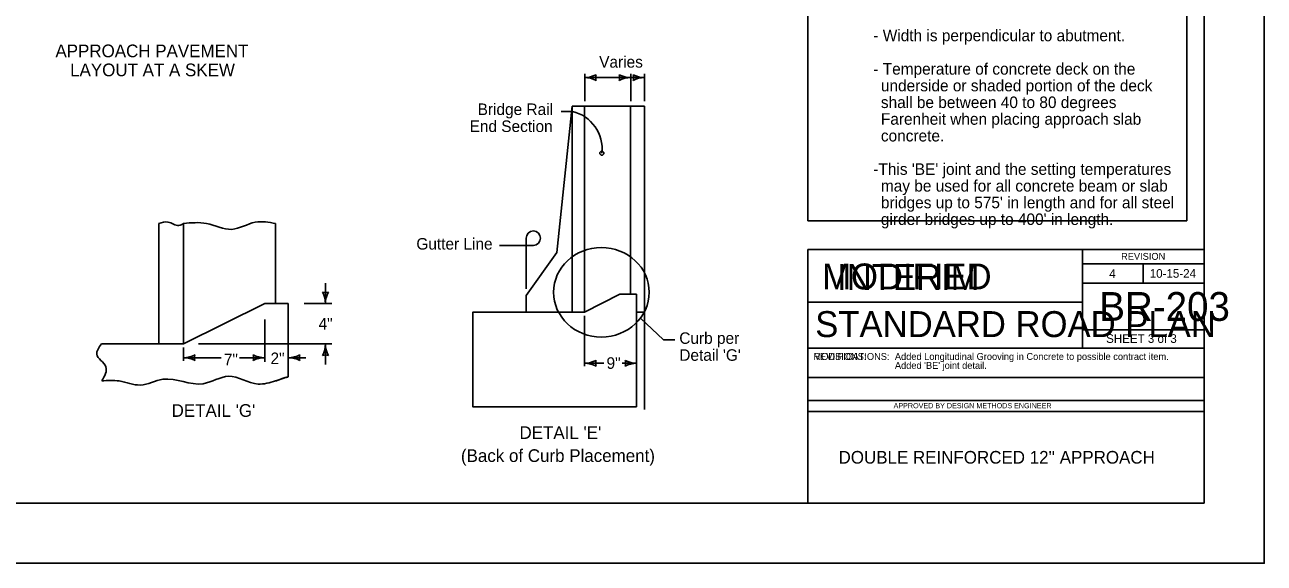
# Model space of a CAD drawing. Extents: x 10130 to 81668, y 5440 to 21644.
# Drawn here: x 18491 to 20643, y 5440 to 6374 of the extents above; entities that cross this region are included whole.
import ezdxf

# ---------------------------------------------------------------- set-up
doc = ezdxf.new("R2010")
doc.units = 0
for name, color, linetype in [('Cell', 7, 'Continuous'), ('dsnCellElements', 7, 'Continuous'), ('dsnNonPlotable', 7, 'Continuous'), ('dsnShtPlotShapeBatchPrint', 7, 'Continuous'), ('dsnstdblockInterim', 7, 'Continuous'), ('dsnStdBlockModified', 7, 'Continuous'), ('dsnStdBlockNotModified', 7, 'Continuous'), ('dsnStdBorder', 7, 'Continuous'), ('dsnStdLabel', 7, 'Continuous'), ('Level 1', 7, 'Continuous'), ('Level 5', 7, 'Continuous')]:
    doc.layers.add(name, color=color, linetype=linetype)

msp = doc.modelspace()

# ---------------------------------------------------------------- linework, layer by layer
at = {"layer": 'Cell'}
msp.add_lwpolyline([(17403.2, 7554.1), (20538.2, 7554.1), (20538.2, 5544.1), (17403.2, 5544.1)], close=True, dxfattribs=at)
at = {"layer": 'dsnCellElements'}
for p, q in [((19361.3, 5983.9), (19361.3, 6003.9)), ((19373.8, 5991.4), (19353.8, 5991.4))]:
    msp.add_line(p, q, dxfattribs=at)
msp.add_circle((19492.7, 6151.4), 3.54, dxfattribs=at)
msp.add_arc((19373.8, 6003.9), 12.5, 270, 180, dxfattribs=at)
at = {"layer": 'dsnNonPlotable'}
for p, q in [((19850.2, 7504.1), (19850.2, 6034.1)), ((20508.2, 7504.1), (20508.2, 6034.1)), ((20508.2, 6034.1), (19850.2, 6034.1))]:
    msp.add_line(p, q, dxfattribs=at)
at = {"layer": 'dsnShtPlotShapeBatchPrint'}
msp.add_lwpolyline([(17298.7, 5439.6), (20642.7, 5439.6), (20642.7, 8023.6), (17298.7, 8023.6)], close=True, dxfattribs=at)
at = {"layer": 'dsnStdBlockNotModified'}
for centre, radius, start, end in [((19462.6, 6325.2), 42.5, 270, 298.0725), ((19498.3, 6282.7), 16.4, 162.2666, 197.7334), ((19507.3, 6282.7), 16.4, 342.2666, 17.7333), ((19542.9, 6325.2), 42.5, 241.9275, 270), ((19531.2, 6282.7), 16.4, 342.2666, 17.7333), ((19566.9, 6325.2), 42.5, 241.9275, 270), ((19462.6, 6240.2), 42.5, 61.9275, 90), ((19542.9, 6240.2), 42.5, 90, 118.0725), ((19566.9, 6240.2), 42.5, 90, 118.0725), ((19012.9, 5925.8), 16.4, 252.2666, 287.7333), ((18970.4, 5890.2), 42.5, 360, 28.0725), ((19055.4, 5890.2), 42.5, 151.9275, 180), ((18970.4, 5820.3), 42.5, 331.9275, 360), ((19055.4, 5820.3), 42.5, 180, 208.0725), ((18766.4, 5838.9), 42.5, 270, 298.0725), ((18766.4, 5753.9), 42.5, 61.9275, 90), ((18802, 5796.4), 16.4, 162.2666, 197.7334), ((18871.8, 5796.4), 16.4, 342.2666, 17.7333), ((18907.5, 5838.9), 42.5, 241.9275, 270), ((18907.5, 5753.9), 42.5, 90, 118.0725), ((18948.4, 5838.9), 42.5, 270, 298.0725), ((18948.4, 5753.9), 42.5, 61.9275, 90), ((18984.1, 5796.4), 16.4, 162.2666, 197.7334), ((19012.9, 5784.7), 16.4, 72.2666, 107.7334), ((19462.6, 5829.2), 42.5, 270, 298.0725), ((19498.3, 5786.7), 16.4, 162.2666, 197.7334), ((19517.7, 5786.7), 16.4, 342.2666, 17.7333), ((19553.3, 5829.2), 42.5, 241.9275, 270), ((19462.6, 5744.2), 42.5, 61.9275, 90), ((19553.3, 5744.2), 42.5, 90, 118.0725)]:
    msp.add_arc(centre, radius, start, end, dxfattribs=at)
at = {"layer": 'dsnStdBorder'}
for p, q in [((19462.9, 6242), (19462.9, 6289.4)), ((19542.9, 6242), (19542.9, 6289.4)), ((19566.9, 6242), (19566.9, 6289.4)), ((19462.6, 6282.7), (19491.7, 6282.7)), ((19462.9, 6282.7), (19542.9, 6282.7)), ((19538.6, 6282.7), (19566.9, 6282.7)), ((19414.6, 5979), (19441.3, 6233)), ((19441.6, 6223.8), (19422.1, 6223.8)), ((19441.3, 6233), (19542.7, 6233)), ((19441.3, 6233), (19441.3, 5875.4)), ((19462.6, 6233), (19462.6, 5875.4)), ((19542.7, 6233), (19542.7, 5906.9)), ((19542.7, 6233), (19566.9, 6233)), ((19566.9, 6233), (19566.9, 5706.6)), ((18723.8, 6029.3), (18723.8, 5820.3)), ((18766.4, 6029.3), (18766.4, 5820.3)), ((18926.4, 6029.3), (18926.4, 5890.2)), ((19314.9, 5991.4), (19353.8, 5991.4)), ((19361.3, 5916), (19361.3, 5983.9)), ((19361.3, 5904.3), (19414.6, 5979)), ((18926.4, 5946.7), (18926.4, 5890.2)), ((19012.9, 5925.9), (19012.9, 5890.2)), ((19542.7, 5938.6), (19542.7, 5906.9)), ((19361.3, 5875.3), (19361.3, 5904.3)), ((19552.9, 5906.9), (19524, 5906.9)), ((19524, 5906.9), (19552.9, 5906.9)), ((19552.9, 5711.2), (19552.9, 5906.9)), ((19552.9, 5906.9), (19552.9, 5711.2)), ((18948.4, 5890.2), (18907.7, 5890.2)), ((18948.4, 5762.9), (18948.4, 5890.2)), ((18975.8, 5890.2), (19023.7, 5890.2)), ((19552.9, 5875.4), (19566.9, 5875.4)), ((18907.5, 5862.9), (18907.5, 5789)), ((19462.6, 5781.5), (19462.6, 5868.8)), ((19559.6, 5865), (19599.6, 5827.3)), ((18765.2, 5820.3), (18624.2, 5820.2)), ((18648.6, 5820.2), (18624.2, 5820.2)), ((18624.5, 5820.3), (18670.4, 5820.2)), ((18670.4, 5820.2), (18648.6, 5820.2)), ((18766.3, 5820.2), (18670.4, 5820.2)), ((18670.4, 5820.2), (18766.3, 5820.2)), ((18766.4, 5820.3), (18765.2, 5820.3)), ((18766.3, 5813.9), (18766.3, 5790.9)), ((18792.2, 5820.3), (19023.7, 5820.3)), ((19012.9, 5820.3), (19012.9, 5784.6)), ((19599.6, 5827.3), (19619.4, 5827.3)), ((18766.4, 5796.4), (18832.1, 5796.4)), ((18863.4, 5796.4), (18907.5, 5796.4)), ((18948.4, 5796.4), (18978.8, 5796.4)), ((19462.6, 5786.7), (19496.3, 5786.7)), ((19528.1, 5786.7), (19553.3, 5786.7))]:
    msp.add_line(p, q, dxfattribs=at)
for points in [[(19462.6, 5875.4), (19524, 5906.9)], [(19462.6, 5875.4), (19524, 5906.9)], [(18907.7, 5890.2), (18766.4, 5820.3), (18766.3, 5820.2)], [(18766.3, 5820.2), (18907.7, 5890.2)], [(18948.4, 5890.2), (18926.4, 5890.2), (18907.7, 5890.2)], [(18948.4, 5762.9), (18948.4, 5762.9), (18948.4, 5890.2)], [(19552.9, 5711.2), (19268.6, 5711.2), (19268.6, 5875.4), (19414.7, 5875.3), (19462.6, 5875.4)], [(19552.9, 5711.2), (19268.6, 5711.2), (19268.6, 5875.4), (19414.7, 5875.3), (19462.6, 5875.4)]]:
    msp.add_lwpolyline(points, dxfattribs=at)
msp.add_arc((19426.5, 6158.9), 66.7, 353.5756, 76.8823, dxfattribs=at)
msp.add_ellipse((19491.9, 5909.9), major_axis=(83, 0), ratio=0.93542, dxfattribs=at)
for points in [[(18723.8, 6029.3), (18739.4, 6031.8), (18758.5, 6025.9), (18766.4, 6029.3)], [(18766.4, 6029.3), (18806.5, 6029.3), (18850.2, 6019.2), (18891.1, 6031.5), (18926.4, 6029.3)], [(18624.2, 5820.2), (18615.9, 5802.6), (18631.7, 5780.5), (18624.5, 5756)], [(18624.2, 5820.2), (18615.9, 5802.6), (18631.7, 5780.5), (18624.5, 5756)], [(18624.5, 5756), (18655, 5756), (18691.2, 5748.9), (18730.8, 5758.9), (18800.8, 5751.3), (18844.6, 5764.1), (18895.9, 5750.7), (18926.4, 5756)], [(18624.5, 5756), (18655, 5756), (18691.2, 5748.9), (18730.8, 5758.9), (18800.8, 5751.3), (18844.6, 5764.1), (18895.9, 5750.7), (18926.4, 5756)], [(18926.4, 5756), (18940.5, 5761), (18945.8, 5762.6)]]:
    msp.add_spline(points, degree=3, dxfattribs=at)
msp.add_open_spline([(18926.4, 5756), (18927.3, 5756.2), (18928.3, 5756.5), (18929.2, 5756.8), (18930.1, 5757.2), (18931, 5757.5), (18931.9, 5757.8), (18933.7, 5758.5), (18935.6, 5759.3), (18937.4, 5760), (18939.2, 5760.7), (18941, 5761.3), (18942.9, 5761.9), (18943.8, 5762.1), (18944.7, 5762.3), (18945.6, 5762.5), (18946.1, 5762.6), (18946.5, 5762.7), (18947, 5762.8), (18947.5, 5762.8), (18947.9, 5762.9), (18948.4, 5762.9)], degree=3, dxfattribs=at)
at = {"layer": 'dsnStdLabel'}
for p, q in [((20327.3, 5984.1), (20327.3, 5892.8)), ((20327.3, 5959.2), (20538.2, 5959.2)), ((20432.7, 5959.2), (20432.7, 5926)), ((20327.3, 5926), (20538.2, 5926)), ((19850.2, 5892.8), (20327.3, 5892.8)), ((20327.3, 5892.8), (20327.3, 5812.8)), ((20538.2, 5845), (20327.3, 5845)), ((19850.2, 5812.8), (20538.2, 5812.8)), ((19850.2, 5761.8), (20538.2, 5761.8)), ((19850.2, 5721.8), (20538.2, 5721.8)), ((19850.2, 5702.8), (20538.2, 5702.8))]:
    msp.add_line(p, q, dxfattribs=at)
msp.add_lwpolyline([(19850.2, 5984.1), (20538.2, 5984.1), (20538.2, 5544.1), (19850.2, 5544.1)], close=True, dxfattribs=at)
msp.add_lwpolyline([(19850.2, 5984.1), (20538.2, 5984.1), (20538.2, 5544.1), (19850.2, 5544.1)], close=True, dxfattribs=at)

# ---------------------------------------------------------------- texts
at = {"layer": 'dsnstdblockInterim'}
msp.add_text('INTERIM', height=45, dxfattribs=at).set_placement((19901.1, 5913.8))
at = {"layer": 'dsnStdBlockModified'}
msp.add_text('(Back of Curb Placement)', height=22, dxfattribs=at).set_placement((19248.1, 5615.4))
at = {"layer": 'dsnStdBlockNotModified'}
msp.add_text('REVISIONS:', height=12, dxfattribs=at).set_placement((19860.2, 5792.5))
at = {"layer": 'dsnStdBorder'}
for s, height, p in [('APPROACH PAVEMENT', 22, (18544.1, 6318)), ('LAYOUT AT A SKEW', 22, (18569.6, 6285)), ('Varies', 20, (19488.1, 6299.9)), ('Bridge Rail ', 20, (19277.1, 6217.7)), ('End Section', 20, (19263.1, 6188.2)), ('Gutter Line', 20, (19170.7, 5984.1)), ('4"', 20, (19000.9, 5845.2)), ('Curb per', 20, (19627.2, 5820.4)), ("Detail 'G'", 20, (19627.2, 5791)), ('7"', 20, (18836.5, 5783.3)), ('2"', 20, (18917.5, 5785.3)), ('9"', 20, (19500.9, 5777.1)), ("DETAIL 'G'", 22, (18745.8, 5693.7)), ("DETAIL 'E'", 22, (19349.7, 5655.4))]:
    msp.add_text(s, height=height, dxfattribs=at).set_placement(p)
at = {"layer": 'dsnStdLabel'}
for s, height, p in [('REVISION', 12, (20394.2, 5966.3)), ('4', 15, (20373.6, 5934.8)), ('10-15-24', 15, (20444, 5935.2)), ('BR-203', 50, (20356.4, 5860.3)), ('STANDARD ROAD PLAN', 45.001, (19863.2, 5832.2)), ('SHEET 3 of 3', 15, (20368.2, 5822.1)), ('Added Longitudinal Grooving in Concrete to possible contract item. ', 12, (20001.5, 5792.5)), ("Added 'BE' joint detail.", 12, (20001.5, 5777)), ('APPROVED BY DESIGN METHODS ENGINEER', 9.003, (19999.2, 5708.6)), ("DOUBLE REINFORCED 12'' APPROACH", 22, (19903.7, 5612.5))]:
    msp.add_text(s, height=height, dxfattribs=at).set_placement(p)
at = {"layer": 'Level 1'}
for s, height, p in [('MODIFIED', 45, (19875.2, 5914.9)), ('MODIFICATIONS:', 12, (19860.2, 5792.5))]:
    msp.add_text(s, height=height, dxfattribs=at).set_placement(p)
at = {"layer": 'Level 5'}
for s, p in [('         - Width is perpendicular to abutment.', (19897.2, 6345.8)), ('         - Temperature of concrete deck on the ', (19897.2, 6287.8)), ('underside or shaded portion of the deck ', (19977.2, 6258.8)), ('shall be between 40 to 80 degrees ', (19977.2, 6229.8)), ('Farenheit when placing approach slab ', (19977.2, 6200.8)), ('concrete.', (19977.2, 6171.8)), ("         -This 'BE' joint and the setting temperatures ", (19897.2, 6113.8)), ('may be used for all concrete beam or slab ', (19977.2, 6084.8)), ("bridges up to 575' in length and for all steel ", (19977.2, 6055.8)), ("girder bridges up to 400' in length.", (19977.2, 6026.8))]:
    msp.add_text(s, height=20, dxfattribs=at).set_placement(p)

doc.saveas('drawing.dxf')
